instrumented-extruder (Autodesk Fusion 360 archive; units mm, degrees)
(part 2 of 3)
sketch "Sketch1" plane through (0, 0, 0) normal (0, 1, 0) x axis (1, 0, 0)
  line L1 (0, 10) -> (0, -2.75)
  line L2 (1.95, 10) -> (0, 10)
  line L3 (2.45, 9.5) -> (1.95, 10)
  line L4 (2.45, 0) -> (2.45, 9.5)
  line L5 (4.75, 0) -> (2.45, 0)
  line L6 (4.75, -0.6) -> (4.75, 0)
  line L7 (2, -2.75) -> (0, -2.75)
  arc A1 centre (0, 2.6419) radius 5.7508 clockwise from (4.75, -0.6) to (2, -2.75)
  point P1 (0, 0)
  point P10 (0, 2.6419)
  point P3 (0, 10)
  point P2 (0, -2.75)
  point P9 (2, -2.75)
  point P7 (4.75, 0)
  point P8 (4.75, -0.6)
  point P5 (2.45, 9.5)
  vertical L1
  perpendicular L1 L2
  perpendicular L2 L4
  perpendicular L4 L5
  perpendicular L5 L6
  perpendicular L1 L7
  coincident P1 L5
  coincident L1 P10
  coincident P1 L1
  dimension "d1" distance P1 P3 = 10
  dimension "d2" distance P1 P2 = 2.75
  dimension "d3" distance P2 P9 = 2 (= "( 4 / 2 ) * 1 mm")
  dimension "d4" distance P7 P8 = 0.6
  dimension "d5" distance L1 P7 = 4.75 (= "( 9.5 / 2 ) * 1 mm")
  dimension "d6" distance P1 L4 = 2.45 (= "( 4.9 / 2 ) * 1 mm")
  dimension "d7" angle L2 L3 = 45
  dimension "d8" distance L2 P5 = 0.5
revolve "Revolve1" sketch "Sketch1" AlongAngle 360
sketch "Sketch2" plane through (0, 0, 2.75) normal (0, 0, 1) x axis (-1, 0, 0)
  line L1 (0, -1.7321) -> (-1.5, -0.866)
  line L2 (1.5, -0.866) -> (0, -1.7321)
  line L3 (1.5, 0.866) -> (1.5, -0.866)
  line L4 (0, 1.7321) -> (1.5, 0.866)
  line L5 (-1.5, 0.866) -> (0, 1.7321)
  line L6 (-1.5, -0.866) -> (-1.5, 0.866)
  circle C1 centre (0, 0) radius 2
  point P2 (0, 0)
  point P9 (0, 0)
  point P5 (1.5, -0.866)
  coincident P2 P9
  vertical L3
  dimension "d10" distance P5 L6 = 3
extrude "Extrude1" cut sketch "Sketch2" profile of L1 L2 L3 L4 L5 L6 to an object offset 0.5

design "PP_SHFT_5x28-91585A562"
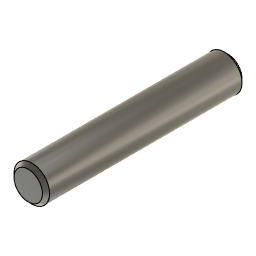
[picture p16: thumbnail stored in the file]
sketch "Sketch1" plane through (0, 0, 0) normal (0, 1, 0) x axis (1, 0, 0)
  circle C1 centre (0, 0) radius 2.5
  point P1 (0, 0)
  point P2 (0, 0)
  coincident P1 P2
  dimension "d1" diameter C1 = 5
extrude "Extrude1" new body sketch "Sketch1" along normal blind 28
chamfer "Chamfer1" distance 0.5

design "Pogo USB Stick"
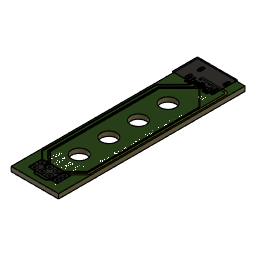
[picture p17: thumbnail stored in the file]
sketch "Outline" plane through (0, 0, 0) normal (0, 0, 1) x axis (1, 0, 0)
  line L1 (16, 0) -> (0, 0)
  line L2 (16, 63) -> (16, 0)
  line L3 (0, 63) -> (16, 63)
  line L4 (0, 0) -> (0, 63)
  line L5 (3.3811, 55.7439) -> (3.38, 55.77)
  line L6 (3.3846, 55.7179) -> (3.3811, 55.7439)
  line L7 (3.3902, 55.6924) -> (3.3846, 55.7179)
  line L8 (3.3981, 55.6674) -> (3.3902, 55.6924)
  line L9 (3.4081, 55.6432) -> (3.3981, 55.6674)
  line L10 (3.4202, 55.62) -> (3.4081, 55.6432)
  line L11 (3.4343, 55.5979) -> (3.4202, 55.62)
  line L12 (3.4502, 55.5772) -> (3.4343, 55.5979)
  line L13 (3.4679, 55.5579) -> (3.4502, 55.5772)
  line L14 (3.4872, 55.5402) -> (3.4679, 55.5579)
  line L15 (3.5079, 55.5243) -> (3.4872, 55.5402)
  line L16 (3.53, 55.5102) -> (3.5079, 55.5243)
  line L17 (3.5532, 55.4981) -> (3.53, 55.5102)
  line L18 (3.5774, 55.4881) -> (3.5532, 55.4981)
  line L19 (3.6024, 55.4802) -> (3.5774, 55.4881)
  line L20 (3.6279, 55.4746) -> (3.6024, 55.4802)
  line L21 (3.6539, 55.4711) -> (3.6279, 55.4746)
  line L22 (3.68, 55.47) -> (3.6539, 55.4711)
  line L23 (3.7061, 55.4711) -> (3.68, 55.47)
  line L24 (3.7321, 55.4746) -> (3.7061, 55.4711)
  line L25 (3.7576, 55.4802) -> (3.7321, 55.4746)
  line L26 (3.7826, 55.4881) -> (3.7576, 55.4802)
  line L27 (3.8068, 55.4981) -> (3.7826, 55.4881)
  line L28 (3.83, 55.5102) -> (3.8068, 55.4981)
  line L29 (3.8521, 55.5243) -> (3.83, 55.5102)
  line L30 (3.8728, 55.5402) -> (3.8521, 55.5243)
  line L31 (3.8921, 55.5579) -> (3.8728, 55.5402)
  line L32 (3.9098, 55.5772) -> (3.8921, 55.5579)
  line L33 (3.9257, 55.5979) -> (3.9098, 55.5772)
  line L34 (3.9398, 55.62) -> (3.9257, 55.5979)
  line L35 (3.9519, 55.6432) -> (3.9398, 55.62)
  line L36 (3.9619, 55.6674) -> (3.9519, 55.6432)
  line L37 (3.9698, 55.6924) -> (3.9619, 55.6674)
  line L38 (3.9754, 55.7179) -> (3.9698, 55.6924)
  line L39 (3.9789, 55.7439) -> (3.9754, 55.7179)
  line L40 (3.98, 55.77) -> (3.9789, 55.7439)
  line L41 (3.98, 56.87) -> (3.98, 55.77)
  line L42 (3.9789, 56.8961) -> (3.98, 56.87)
  line L43 (3.9754, 56.9221) -> (3.9789, 56.8961)
  line L44 (3.9698, 56.9476) -> (3.9754, 56.9221)
  line L45 (3.9619, 56.9726) -> (3.9698, 56.9476)
  line L46 (3.9519, 56.9968) -> (3.9619, 56.9726)
  line L47 (3.9398, 57.02) -> (3.9519, 56.9968)
  line L48 (3.9257, 57.0421) -> (3.9398, 57.02)
  line L49 (3.9098, 57.0628) -> (3.9257, 57.0421)
  line L50 (3.8921, 57.0821) -> (3.9098, 57.0628)
  line L51 (3.8728, 57.0998) -> (3.8921, 57.0821)
  line L52 (3.8521, 57.1157) -> (3.8728, 57.0998)
  line L53 (3.83, 57.1298) -> (3.8521, 57.1157)
  line L54 (3.8068, 57.1419) -> (3.83, 57.1298)
  line L55 (3.7826, 57.1519) -> (3.8068, 57.1419)
  line L56 (3.7576, 57.1598) -> (3.7826, 57.1519)
  line L57 (3.7321, 57.1654) -> (3.7576, 57.1598)
  line L58 (3.7061, 57.1689) -> (3.7321, 57.1654)
  line L59 (3.68, 57.17) -> (3.7061, 57.1689)
  line L60 (3.6539, 57.1689) -> (3.68, 57.17)
  line L61 (3.6279, 57.1654) -> (3.6539, 57.1689)
  line L62 (3.6024, 57.1598) -> (3.6279, 57.1654)
  line L63 (3.5774, 57.1519) -> (3.6024, 57.1598)
  line L64 (3.5532, 57.1419) -> (3.5774, 57.1519)
  line L65 (3.53, 57.1298) -> (3.5532, 57.1419)
  line L66 (3.5079, 57.1157) -> (3.53, 57.1298)
  line L67 (3.4872, 57.0998) -> (3.5079, 57.1157)
  line L68 (3.4679, 57.0821) -> (3.4872, 57.0998)
  line L69 (3.4502, 57.0628) -> (3.4679, 57.0821)
  line L70 (3.4343, 57.0421) -> (3.4502, 57.0628)
  line L71 (3.4202, 57.02) -> (3.4343, 57.0421)
  line L72 (3.4081, 56.9968) -> (3.4202, 57.02)
  line L73 (3.3981, 56.9726) -> (3.4081, 56.9968)
  line L74 (3.3902, 56.9476) -> (3.3981, 56.9726)
  line L75 (3.3846, 56.9221) -> (3.3902, 56.9476)
  line L76 (3.3811, 56.8961) -> (3.3846, 56.9221)
  line L77 (3.38, 56.87) -> (3.3811, 56.8961)
  line L78 (3.38, 55.77) -> (3.38, 56.87)
  line L79 (12.0211, 55.7439) -> (12.02, 55.77)
  line L80 (12.0246, 55.7179) -> (12.0211, 55.7439)
  line L81 (12.0302, 55.6924) -> (12.0246, 55.7179)
  line L82 (12.0381, 55.6674) -> (12.0302, 55.6924)
  line L83 (12.0481, 55.6432) -> (12.0381, 55.6674)
  line L84 (12.0602, 55.62) -> (12.0481, 55.6432)
  line L85 (12.0743, 55.5979) -> (12.0602, 55.62)
  line L86 (12.0902, 55.5772) -> (12.0743, 55.5979)
  line L87 (12.1079, 55.5579) -> (12.0902, 55.5772)
  line L88 (12.1272, 55.5402) -> (12.1079, 55.5579)
  line L89 (12.1479, 55.5243) -> (12.1272, 55.5402)
  line L90 (12.17, 55.5102) -> (12.1479, 55.5243)
  line L91 (12.1932, 55.4981) -> (12.17, 55.5102)
  line L92 (12.2174, 55.4881) -> (12.1932, 55.4981)
  line L93 (12.2424, 55.4802) -> (12.2174, 55.4881)
  line L94 (12.2679, 55.4746) -> (12.2424, 55.4802)
  line L95 (12.2939, 55.4711) -> (12.2679, 55.4746)
  line L96 (12.32, 55.47) -> (12.2939, 55.4711)
  line L97 (12.3461, 55.4711) -> (12.32, 55.47)
  line L98 (12.3721, 55.4746) -> (12.3461, 55.4711)
  line L99 (12.3976, 55.4802) -> (12.3721, 55.4746)
  line L100 (12.4226, 55.4881) -> (12.3976, 55.4802)
  line L101 (12.4468, 55.4981) -> (12.4226, 55.4881)
  line L102 (12.47, 55.5102) -> (12.4468, 55.4981)
  line L103 (12.4921, 55.5243) -> (12.47, 55.5102)
  line L104 (12.5128, 55.5402) -> (12.4921, 55.5243)
  line L105 (12.5321, 55.5579) -> (12.5128, 55.5402)
  line L106 (12.5498, 55.5772) -> (12.5321, 55.5579)
  line L107 (12.5657, 55.5979) -> (12.5498, 55.5772)
  line L108 (12.5798, 55.62) -> (12.5657, 55.5979)
  line L109 (12.5919, 55.6432) -> (12.5798, 55.62)
  line L110 (12.6019, 55.6674) -> (12.5919, 55.6432)
  line L111 (12.6098, 55.6924) -> (12.6019, 55.6674)
  line L112 (12.6154, 55.7179) -> (12.6098, 55.6924)
  line L113 (12.6189, 55.7439) -> (12.6154, 55.7179)
  line L114 (12.62, 55.77) -> (12.6189, 55.7439)
  line L115 (12.62, 56.87) -> (12.62, 55.77)
  line L116 (12.6189, 56.8961) -> (12.62, 56.87)
  line L117 (12.6154, 56.9221) -> (12.6189, 56.8961)
  line L118 (12.6098, 56.9476) -> (12.6154, 56.9221)
  line L119 (12.6019, 56.9726) -> (12.6098, 56.9476)
  line L120 (12.5919, 56.9968) -> (12.6019, 56.9726)
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canvas "Canvas1" bodies "Board"
canvas "Canvas2" bodies "Board"
pcbhole "PCBHole1" HoleDepth 1.605 HoleDiameter 5.25 TipAngle 10313.2
pcbhole "PCBHole2" HoleDepth 1.605 HoleDiameter 5.25 TipAngle 10313.2
pcbhole "PCBHole3" HoleDepth 1.605 HoleDiameter 5.25 TipAngle 10313.2
pcbhole "PCBHole4" HoleDepth 1.605 HoleDiameter 5.25 TipAngle 10313.2
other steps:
extrude "Extrude1" sketch "Outline" blind 1.5 bodies "Board"
pcbextrude "PCBExtrude1"
pcbextrude "PCBExtrude1"
pcbextrude "PCBExtrude1"
box_primitive "BoxPrimitive1" DistanceX 9.7028 DistanceY 4.6228 DistanceZ 0.1 OffsetDistanceX 0 OffsetDistanceY 0
box_primitive "BoxPrimitive1" DistanceX 13.575 DistanceY 8.48 DistanceZ 0.1 OffsetDistanceX 0 OffsetDistanceY 0
pcbextrude "PCBExtrude1"
pcbextrude "PCBExtrude1"
pcbhole "PCBHole1"
pcbhole "PCBHole1"
pcbhole "PCBHole1" HoleDepth 1.606 HoleDiameter 5.25 TipAngle 10313.2
pcbhole "PCBHole1" HoleDepth 1.606 HoleDiameter 5.25 TipAngle 10313.2
pcbextrude "PCBExtrude2" bodies "CopperHoles"
pcbhole "PCBHole2" HoleDepth 1.606 HoleDiameter 5.25 TipAngle 10313.2
pcbhole "PCBHole2" HoleDepth 1.606 HoleDiameter 5.25 TipAngle 10313.2
pcbhole "PCBHole3" HoleDepth 1.606 HoleDiameter 5.25 TipAngle 10313.2
pcbhole "PCBHole3" HoleDepth 1.606 HoleDiameter 5.25 TipAngle 10313.2
pcbhole "PCBHole1"
pcbhole "PCBHole4" HoleDepth 1.606 HoleDiameter 5.25 TipAngle 10313.2
pcbhole "PCBHole4" HoleDepth 1.606 HoleDiameter 5.25 TipAngle 10313.2
create_component "CreateComponent1"
create_component "CreateComponent2"
create_component "CreateComponent3"
create_component "CreateComponent4"
create_component "CreateComponent5"
create_component "CreateComponent6"
create_component "CreateComponent1"
create_component "CreateComponent2"
as_built_joint "As-built1"
named bodies: "Board", "CopperHoles"

design "HW_M5-Washer"
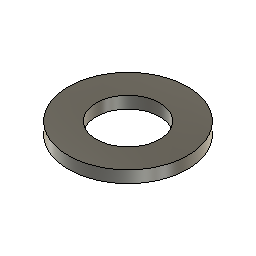
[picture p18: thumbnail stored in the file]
sketch "Sketch1" plane through (0, 0, 0) normal (0, 1, 0) x axis (1, 0, 0)
  line L1 (5, 0) -> (2.65, 0)
  line L2 (5, -1) -> (5, 0)
  line L3 (2.65, -1) -> (5, -1)
  line L4 (2.65, 0) -> (2.65, -1)
  point P1 (0, 0)
  point P2 (2.65, 0)
  point P5 (2.65, -1)
  horizontal L1
  vertical L2
  horizontal L3
  vertical L4
  coincident P1 L1
  dimension "d1" distance P2 P5 = 1
  dimension "d2" distance P1 L4 = 2.65 (= "( 5.3 / 2 ) * 1 mm")
  dimension "d3" distance P1 L2 = 5 (= "( 10 / 2 ) * 1 mm")
revolve "Revolve1" sketch "Sketch1" AlongAngle 360

design "AS_Tool-Blank" references "Pogo USB Stick", "HW_M5x10-BHCS", "HW_M5x08-BHCS", "HW_M5x10-SHCS"
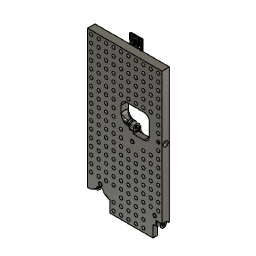
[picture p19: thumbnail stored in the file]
sketch "Profile" plane through (0, 0, 0) normal (1, 0, 0) x axis (0, 1, 0)
  line L1 (-10, 0) -> (0, 0)
  line L2 (-10, 200) -> (-10, 0)
  line L3 (0, 200) -> (-10, 200)
  line L4 (0, 0) -> (0, 200)
  line L5 (-5, 200) -> (-5, 0)
  line L6 (-0.8, 19.3115) -> (0, 19.3115)
  line L7 (-10, 22.4) -> (-5, 22.4)
  line L8 (-10, 15.7813) -> (-9.2, 15.7813)
  line L9 (0, 16.2825) -> (-1.6412, 14.6412)
  circle C1 centre (-5, 18) radius 2.2
  circle C2 centre (-5, 18) radius 4.25
  arc A1 centre (-5, 18) radius 4.4 clockwise from (-5, 22.4) to (-0.8, 19.3115)
  arc A2 centre (-5, 18) radius 4.75 clockwise from (-1.6412, 14.6412) to (-9.2, 15.7813)
  point P1 (0, 0)
  point P2 (0, 0)
  point P8 (-5, 0)
  point P9 (-5, 200)
  point P6 (-5, 18)
  point P10 (0, 19.3115)
  point P12 (-5, 18)
  point P14 (-10, 22.4)
  point P15 (-5, 18)
  point P18 (-10, 15.7813)
  point P19 (0, 16.2825)
  point P4 (-10, 200)
  point P5 (0, 200)
  point P3 (-10, 0)
  point P11 (-0.8, 19.3115)
  horizontal L1
  vertical L2
  horizontal L3
  vertical L4
  coincident P1 P2
  concentric C1 C2
  midpoint L1 P8
  midpoint L3 P9
  coincident P6 L5
  coincident L4 P10
  perpendicular L4 L6
  coincident P6 P12
  coincident L2 P14
  tangent A1 L7
  perpendicular L2 L7
  coincident P12 P15
  coincident L2 P18
  perpendicular L2 L8
  equal L6 L8
  coincident L4 P19
  tangent A2 L9
  dimension "d1" distance P4 P5 = 10
  dimension "d2" distance P3 P4 = 200
  dimension "d3" distance P3 P6 = 18
  dimension "d5" diameter C1 = 4.4
  dimension "d6" diameter C2 = 8.5
  dimension "d7" distance C2 A1 = 0.15
  dimension "d20" distance P10 P11 = 0.8
  dimension "d21" angle L5 L9 = 45
  dimension "d22" distance C2 A2 = 0.5
  dimension "d276" alignAngle = 0
  dimension "d277" alignOffsetX = 0
  dimension "d278" alignOffsetY = 0
  dimension "d279" alignOffsetZ = 1.6
  dimension "d280" alignAngle = 0
  dimension "d281" alignOffsetX = 0
  dimension "d282" alignOffsetY = 0
  dimension "d283" alignOffsetZ = 1.6
  dimension "d284" alignAngle = 0
  dimension "d285" alignOffsetX = 0
  dimension "d286" alignOffsetY = 0
  dimension "d287" alignOffsetZ = 1.6
extrude "Extrude1" new body sketch "Profile" profile of L1 L2 L3 L4 C1 L6 A1 L7 distance 100
sketch "Face" plane through (0, -10, 0) normal (0, -1, 0) x axis (1, 0, 0)
  line L1 (50, 0) -> (-50, 0)
  line L2 (50, 200) -> (50, 0)
  line L3 (-50, 200) -> (50, 200)
  line L4 (-50, 0) -> (-50, 200)
  line L5 (-45.5466, 15) -> (-50, 15)
  line L6 (-36.4534, 20.25) -> (-45.5466, 15)
  line L7 (-20.4534, 15) -> (-29.5466, 20.25)
  line L8 (-20, 0) -> (-20, 15)
  line L9 (-33, 3.7686) -> (-41, 17.625)
  line L10 (-33, 3.7686) -> (-25, 17.625)
  line L11 (-33, 14.2686) -> (-33, 3.7686)
  line L12 (-46.5, 27.1513) -> (-41, 17.625)
  line L13 (-20.4534, 15) -> (-20, 15)
  line L14 (0, 0) -> (0, 98)
  line L15 (6, 107.75) -> (6, 118.25)
  line L16 (33, 140) -> (33, 107.75)
  line L17 (-5, 140) -> (33, 140)
  line L18 (-5, 107.75) -> (-5, 140)
  line L19 (33, 107.75) -> (-5, 107.75)
  line L20 (10, 98) -> (10, 107.75)
  line L21 (10, 98) -> (0, 98)
  line L22 (-5, 118.25) -> (6, 118.25)
  arc A1 centre (-33, 14.2686) radius 6.9067 clockwise from (-36.4534, 20.25) to (-29.5466, 20.25)
  circle C1 centre (-33, 27) radius 2.2
  circle C2 centre (40, 27) radius 2.2
  circle C3 centre (-33, 27) radius 5
  circle C4 centre (40, 27) radius 5
  circle C5 centre (10, 98) radius 2.2
  circle C6 centre (10, 98) radius 5
  point P6 (-50, 15)
  point P12 (-20, 0)
  point P14 (-41, 17.625)
  point P16 (-25, 17.625)
  point P13 (-33, 14.2686)
  point P17 (-33, 14.2686)
  point P10 (-20.4534, 15)
  point P19 (-20.4534, 15)
  point P22 (0, 0)
  point P27 (0, 0)
  point P30 (6, 107.75)
  point P28 (10, 98)
  point P36 (10, 98)
  point P35 (10, 107.75)
  point P37 (10, 98)
  point P38 (-5, 118.25)
  point P39 (6, 113)
  point P9 (-29.5466, 20.25)
  point P18 (-46.5, 27.1513)
  point P2 (-50, 0)
  point P15 (-33, 3.7686)
  point P1 (0, 0)
  point P20 (-33, 27)
  point P21 (40, 27)
  point P29 (6, 118.25)
  point P31 (33, 107.75)
  point P32 (33, 140)
  point P25 (10, 98)
  point P26 (0, 98)
  point P34 (-5, 107.75)
  coincident L4 P6
  perpendicular L4 L5
  coincident L1 P12
  perpendicular L1 L8
  tangent L7 A1
  tangent L6 A1
  midpoint L6 P14
  perpendicular L6 L9
  midpoint L7 P16
  perpendicular L7 L10
  coincident P13 P17
  vertical L11
  coincident L5 P10
  perpendicular L6 L12
  perpendicular L8 L13
  coincident P10 P19
  concentric C1 C3
  concentric C2 C4
  equal C3 C4
  equal C1 C2
  coincident P22 P27
  vertical L14
  equal C2 C5
  concentric C5 C6
  equal C4 C6
  vertical L15
  perpendicular L16 L17
  perpendicular L16 L19
  coincident P30 L19
  horizontal L19
  coincident P28 P36
  vertical L20
  vertical L18
  coincident L19 P35
  coincident P28 P37
  perpendicular L20 L21
  coincident L18 P38
  perpendicular L18 L22
  midpoint L15 P39
  dimension "d35" radius A1 = 6.9067
  dimension "d37" distance P9 P10 = 10.5
  dimension "d39" distance P14 P18 = 11
  dimension "d40" distance P2 P6 = 15
  dimension "d41" angle L9 L11 = 30
  dimension "d42" distance P2 P15 = 17
  dimension "d43" distance P12 P15 = 13
  dimension "d45" distance P14 P16 = 16
  dimension "d46" distance P1 P20 = 33
  dimension "d47" distance P1 P21 = 40
  dimension "d48" distance P20 P22 = 27
  dimension "d51" distance P1 P21 = 27
  dimension "d52" diameter C2 = 4.4
  dimension "d53" diameter C4 = 10
  dimension "d101" distance P29 P30 = 10.5
  dimension "d188" distance P31 P32 = 32.25
  dimension "d189" distance P1 P31 = 107.75
  dimension "d193" distance P31 P35 = 23
  dimension "d214" distance P1 L17 = 140
  dimension "d215" distance P25 P27 = 98
  dimension "d216" distance P26 P37 = 10
  dimension "d217" distance P27 P39 = 113 (= "98 mm + 15 mm")
  dimension "d218" distance P35 P39 = 4
  dimension "d219" distance P26 P34 = 5
extrude "Extrude7" cut sketch "Face" profile of L1 L4 L5 L6 L7 L8 A1 L13 C1 C2 C5 L15 L16 L17 L18 L19 L22 to an object
hole "Hole1" HoleDepth 11 HoleDiameter 4.4 TipAngle 118 CSDiameter 5 CSAngle 90
hole "Hole2" HoleDepth 11 HoleDiameter 4.4 TipAngle 118 CSDiameter 5 CSAngle 90
extrude "Extrude4" sketch "Profile" profile of L1 L2 L4 C1 L6 A1 L7 A2 L8 L9 blind -8
extrude "Extrude5" sketch "Profile" profile of L1 L2 L4 A2 L8 L9 blind -4
extrude "Extrude6" sketch "Profile" profile of C1 blind -16.5
chamfer "Chamfer2" distance 0.5
fillet "Fillet1" radius 3.2
chamfer "Chamfer9" distance 0.5
chamfer "Chamfer3" distance 0.6
work_plane "WorkPlane1" sketch "Profile" AlongDistance -33
sketch "Left Cleat Slice" plane through (-33, 0, 0) normal (1, 0, 0) x axis (0, 1, 0)
  line L1 (-20.6308, 24.2665) -> (5.35, 9.2665)
  line L2 (-7.7792, 0) -> (0, 0)
  line L3 (-18.0058, 28.8131) -> (-20.6308, 24.2665)
  line L4 (7.975, 13.8131) -> (-18.0058, 28.8131)
  line L5 (5.35, 9.2665) -> (7.975, 13.8131)
  point P1 (0, 0)
  point P4 (0, 0)
  point P2 (5.35, 9.2665)
  point P8 (5.35, 9.2665)
  point P3 (-20.6308, 24.2665)
  point P6 (-18.0058, 28.8131)
  coincident P1 P4
  horizontal L2
  perpendicular L1 L3
  perpendicular L3 L4
  perpendicular L1 L5
  coincident P2 P8
  coincident P1 L5
  dimension "d159" angle L1 L2 = 30
  dimension "d160" distance P3 P6 = 5.25
  dimension "d161" distance P1 L1 = 10.7
  dimension "d162" distance P2 P3 = 30
revolve "Revolve1" sketch "Left Cleat Slice" AlongAngle 360
sketch "Sketch12" plane through (6, 0, 0) normal (1, 0, 0) x axis (0, 1, 0)
  line L1 (0, 118.25) -> (0, 107.75)
  line L2 (-10, 118.25) -> (0, 118.25)
  line L3 (-10, 107.75) -> (-10, 118.25)
  line L4 (0, 107.75) -> (-10, 107.75)
  line L5 (0, 113) -> (-10, 113)
  line L6 (0, 114.7175) -> (-1.6412, 116.3588)
  line L7 (-10, 113.8397) -> (-9.1136, 115.375)
  line L8 (0, 112.8603) -> (-1.1895, 110.8)
  line L9 (-10, 110.8061) -> (-7.2, 109.1895)
  circle C1 centre (-5, 113) radius 2.2
  arc A1 centre (-5, 113) radius 4.75 clockwise from (-9.1136, 115.375) to (-1.6412, 116.3588)
  circle C2 centre (-5, 113) radius 4.25
  arc A2 centre (-5, 113) radius 4.4 clockwise from (-1.1895, 110.8) to (-7.2, 109.1895)
  point P6 (-10, 113)
  point P7 (0, 113)
  point P8 (-5, 113)
  point P9 (-5, 113)
  point P12 (0, 114.7175)
  point P14 (-10, 113.8397)
  point P15 (-5, 113)
  point P18 (0, 112.8603)
  point P19 (-10, 110.8061)
  midpoint L3 P6
  midpoint L1 P7
  midpoint L5 P8
  coincident P8 P9
  tangent A1 L6
  coincident L1 P12
  concentric C1 C2
  coincident L3 P14
  tangent A1 L7
  coincident P8 P15
  coincident L1 P18
  tangent A2 L8
  coincident L3 P19
  tangent A2 L9
  dimension "d220" diameter C1 = 4.4
  dimension "d223" angle L1 L6 = 45
  dimension "d225" diameter C2 = 8.5
  dimension "d226" distance A1 C2 = 0.5
  dimension "d227" angle L3 L7 = 30
  dimension "d235" angle L1 L8 = 30
  dimension "d236" distance C2 A2 = 0.15
  dimension "d237" angle L3 L9 = 60
extrude "Extrude21" cut sketch "Sketch12" profile of C1 against normal blind 16
extrude "Extrude22" cut sketch "Sketch12" profile of L1 L2 L3 A1 L6 L7 to an object
chamfer "Chamfer19" distance 0.5 distance 1.5
chamfer "Chamfer20" distance 0.5
extrude "Extrude23" add sketch "Sketch12" profile of L1 L3 L4 A2 L8 L9 along normal blind 5.5
chamfer "Chamfer21" distance 0.4
extrude "Extrude24" cut sketch "Sketch12" profile of C1 to an object
offset_faces "OffsetFaces2" distance -1.25
chamfer "Chamfer23" distance 4
component_insert "Component Insert1"
component_insert "Component Insert2"
component_insert "Component Insert3"
component_insert "Component Insert4"
component_insert "Component Insert5"
joint "Assemble1" alignAngle 180 alignOffsetX 0 alignOffsetY 0 alignOffsetZ 0
joint "Assemble2" alignAngle 180 alignOffsetX 0 alignOffsetY 0 alignOffsetZ 0
joint "Assemble3" alignAngle 0 alignOffsetX 0 alignOffsetY 0 alignOffsetZ 0
joint "Assemble4" alignAngle 0 alignOffsetX 0 alignOffsetY 0 alignOffsetZ 0
joint "Assemble5" alignAngle 0 alignOffsetX 0 alignOffsetY 0 alignOffsetZ 0
component_insert "Component Insert6"
component_insert "Component Insert7"
joint "Assemble6" alignAngle 180 alignOffsetX 0 alignOffsetY 0 alignOffsetZ 0
joint "Assemble8" alignAngle 180 alignOffsetX 0 alignOffsetY 0 alignOffsetZ 0
sketch "Sketch10" plane through (0, 0, 0) normal (0, 1, 0) x axis (1, 0, 0)
  dimension "d180" = 5
  dimension "d181" = 12.5
  dimension "d182" = 22.5
extrude "Extrude16" sketch "Sketch10" blind -0.6
chamfer "Chamfer22" distance 3
fillet "Fillet9" ChordLen 10
fillet "Fillet10" ChordLen 5
fillet "Fillet11" ChordLen 5
sketch "Grid" plane through (0, 0, 0) normal (0, 1, 0) x axis (1, 0, 0)
  circle C1 centre (-45, -5) radius 2.2
  circle C2 centre (-35, -5) radius 2.2
  circle C3 centre (-25, -5) radius 2.2
  circle C4 centre (-15, -5) radius 2.2
  circle C5 centre (-5, -5) radius 2.2
  circle C6 centre (5, -5) radius 2.2
  circle C7 centre (15, -5) radius 2.2
  circle C8 centre (25, -5) radius 2.2
  circle C9 centre (35, -5) radius 2.2
  circle C10 centre (45, -5) radius 2.2
  circle C11 centre (-45, -15) radius 2.2
  circle C12 centre (-35, -15) radius 2.2
  circle C13 centre (-25, -15) radius 2.2
  circle C14 centre (-15, -15) radius 2.2
  circle C15 centre (-5, -15) radius 2.2
  circle C16 centre (5, -15) radius 2.2
  circle C17 centre (15, -15) radius 2.2
  circle C18 centre (25, -15) radius 2.2
  circle C19 centre (35, -15) radius 2.2
  circle C20 centre (45, -15) radius 2.2
  circle C21 centre (-45, -25) radius 2.2
  circle C22 centre (-35, -25) radius 2.2
  circle C23 centre (-25, -25) radius 2.2
  circle C24 centre (-15, -25) radius 2.2
  circle C25 centre (-5, -25) radius 2.2
  circle C26 centre (5, -25) radius 2.2
  circle C27 centre (15, -25) radius 2.2
  circle C28 centre (25, -25) radius 2.2
  circle C29 centre (35, -25) radius 2.2
  circle C30 centre (45, -25) radius 2.2
  circle C31 centre (-45, -35) radius 2.2
  circle C32 centre (-35, -35) radius 2.2
  circle C33 centre (-25, -35) radius 2.2
  circle C34 centre (-15, -35) radius 2.2
  circle C35 centre (-5, -35) radius 2.2
  circle C36 centre (5, -35) radius 2.2
  circle C37 centre (15, -35) radius 2.2
  circle C38 centre (25, -35) radius 2.2
  circle C39 centre (35, -35) radius 2.2
  circle C40 centre (45, -35) radius 2.2
  circle C41 centre (-45, -45) radius 2.2
  circle C42 centre (-35, -45) radius 2.2
  circle C43 centre (-25, -45) radius 2.2
  circle C44 centre (-15, -45) radius 2.2
  circle C45 centre (-5, -45) radius 2.2
  circle C46 centre (5, -45) radius 2.2
  circle C47 centre (15, -45) radius 2.2
  circle C48 centre (25, -45) radius 2.2
  circle C49 centre (35, -45) radius 2.2
  circle C50 centre (45, -45) radius 2.2
  circle C51 centre (-45, -55) radius 2.2
  circle C52 centre (-35, -55) radius 2.2
  circle C53 centre (-25, -55) radius 2.2
  circle C54 centre (-15, -55) radius 2.2
  circle C55 centre (-5, -55) radius 2.2
  circle C56 centre (5, -55) radius 2.2
  circle C57 centre (15, -55) radius 2.2
  circle C58 centre (25, -55) radius 2.2
  circle C59 centre (35, -55) radius 2.2
  circle C60 centre (45, -55) radius 2.2
  circle C61 centre (-45, -65) radius 2.2
  circle C62 centre (-35, -65) radius 2.2
  circle C63 centre (-25, -65) radius 2.2
  circle C64 centre (-15, -65) radius 2.2
  circle C65 centre (-5, -65) radius 2.2
  circle C66 centre (5, -65) radius 2.2
  circle C67 centre (15, -65) radius 2.2
  circle C68 centre (25, -65) radius 2.2
  circle C69 centre (35, -65) radius 2.2
  circle C70 centre (45, -65) radius 2.2
  circle C71 centre (-45, -75) radius 2.2
  circle C72 centre (-35, -75) radius 2.2
  circle C73 centre (-25, -75) radius 2.2
  circle C74 centre (-15, -75) radius 2.2
  circle C75 centre (-5, -75) radius 2.2
  circle C76 centre (5, -75) radius 2.2
  circle C77 centre (15, -75) radius 2.2
  circle C78 centre (25, -75) radius 2.2
  circle C79 centre (35, -75) radius 2.2
  circle C80 centre (45, -75) radius 2.2
  circle C81 centre (-45, -85) radius 2.2
  circle C82 centre (-35, -85) radius 2.2
  circle C83 centre (-25, -85) radius 2.2
  circle C84 centre (-15, -85) radius 2.2
  circle C85 centre (-5, -85) radius 2.2
  circle C86 centre (5, -85) radius 2.2
  circle C87 centre (15, -85) radius 2.2
  circle C88 centre (25, -85) radius 2.2
  circle C89 centre (35, -85) radius 2.2
  circle C90 centre (45, -85) radius 2.2
  circle C91 centre (-45, -95) radius 2.2
  circle C92 centre (-35, -95) radius 2.2
  circle C93 centre (-25, -95) radius 2.2
  circle C94 centre (-15, -95) radius 2.2
  circle C95 centre (-5, -95) radius 2.2
  circle C96 centre (5, -95) radius 2.2
  circle C97 centre (15, -95) radius 2.2
  circle C98 centre (25, -95) radius 2.2
  circle C99 centre (35, -95) radius 2.2
  circle C100 centre (45, -95) radius 2.2
  circle C101 centre (-45, -105) radius 2.2
  circle C102 centre (-35, -105) radius 2.2
  circle C103 centre (-25, -105) radius 2.2
  circle C104 centre (-15, -105) radius 2.2
  circle C105 centre (-5, -105) radius 2.2
  circle C106 centre (5, -105) radius 2.2
  circle C107 centre (15, -105) radius 2.2
  circle C108 centre (25, -105) radius 2.2
  circle C109 centre (35, -105) radius 2.2
  circle C110 centre (45, -105) radius 2.2
  circle C111 centre (-45, -115) radius 2.2
  circle C112 centre (-35, -115) radius 2.2
  circle C113 centre (-25, -115) radius 2.2
  circle C114 centre (-15, -115) radius 2.2
  circle C115 centre (-5, -115) radius 2.2
  circle C116 centre (5, -115) radius 2.2
  circle C117 centre (15, -115) radius 2.2
  circle C118 centre (25, -115) radius 2.2
  circle C119 centre (35, -115) radius 2.2
  circle C120 centre (45, -115) radius 2.2
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  point P1 (0, 0)
  point P2 (-45, -5)
  dimension "d70" distance P1 P2 = 45
  dimension "d71" distance P1 P2 = 5
  dimension "d72" diameter C1 = 4.4
  dimension "d75" R-Pattern1-uDistance = 10
  dimension "d76" R-Pattern1-vDistance = -10
extrude "Extrude15" cut sketch "Grid" to an object
component_insert "Component Insert13"
joint "Assemble15" alignAngle 0 alignOffsetX 0 alignOffsetY 0 alignOffsetZ 0
component_insert "Component Insert14"
joint "Assemble16" alignAngle 0 alignOffsetX 0 alignOffsetY 0 alignOffsetZ 0
component_insert "Component Insert15"
joint "Assemble17" alignAngle 0 alignOffsetX 0 alignOffsetY 0 alignOffsetZ 0
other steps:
joint_origin "JointOrigin1"
joint_origin "JointOrigin2"
joint_origin "JointOrigin3"
joint_origin "JointOrigin4"
joint_origin "JointOrigin5"
joint_origin "JointOrigin6"
joint_origin "JointOrigin10"
joint_origin "JointOrigin22"
named bodies: "HP-Tool-Blank"

design "PP_SPRN_5-10-25_1804N11"
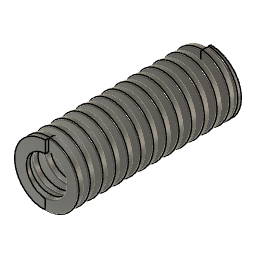
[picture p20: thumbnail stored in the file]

design "AS_Hotend-Extruder" references "PP_SPRN_5-10-25_1804N11", "HW_M5-Washer", "PP_TRNS_Bondtech-Mini-Gears", "HW_M5x60-SHCS", "PP_ACTU_N17-Stepper"
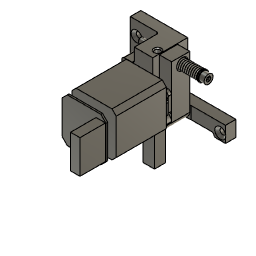
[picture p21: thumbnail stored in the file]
sketch "Sketch1" plane through (0, 0, 0) normal (0, 1, 0) x axis (1, 0, 0)
  line L1 (16.9, -21.15) -> (-25.4, -21.15)
  line L2 (16.9, 21.15) -> (16.9, -21.15)
  line L3 (-25.4, 21.15) -> (16.9, 21.15)
  line L4 (-25.4, -21.15) -> (-25.4, 21.15)
  line L5 (16.9, 21.15) -> (-25.4, -21.15)
  line L6 (-25.4, 21.15) -> (16.9, -21.15)
  line L7 (4.25, 0) -> (-4.25, 0)
  line L8 (11.25, -15.5) -> (-19.75, -15.5)
  line L9 (11.25, 15.5) -> (11.25, -15.5)
  line L10 (-19.75, 15.5) -> (11.25, 15.5)
  line L11 (-19.75, -15.5) -> (-19.75, 15.5)
  line L12 (4.25, 0) -> (4.25, 4.5)
  line L13 (6.25, 4.5) -> (4.25, 4.5)
  line L14 (6.25, 15.5) -> (6.25, 4.5)
  line L15 (16.25, -35) -> (16.25, 15.5)
  line L16 (4.6265, -35) -> (16.25, -35)
  line L17 (4.6265, -4.4842) -> (4.6265, -35)
  line L18 (7.8765, -8) -> (13, -4)
  line L19 (16.25, 9.25) -> (6.25, 9.25)
  line L20 (16.25, 9.5) -> (6.25, 9.5)
  line L21 (16.25, -11.25) -> (4.6265, -11.25)
  line L22 (16.25, -11.5) -> (4.6265, -11.5)
  line L23 (-13.75, -35) -> (3.8765, -35)
  line L24 (-13.75, -21.4) -> (-13.75, -35)
  line L25 (-41, -21.4) -> (-13.75, -21.4)
  line L26 (-41, 21.4) -> (-41, -21.4)
  line L27 (5.5, 21.4) -> (-41, 21.4)
  line L28 (5.5, 5.25) -> (5.5, 21.4)
  line L29 (4.25, 5.25) -> (5.5, 5.25)
  line L30 (3.8765, -35) -> (3.8765, -5.2367)
  line L31 (0.25, 3.4004) -> (-0.25, 3.4004)
  line L32 (0, 3.4004) -> (0, 0)
  line L33 (17.15, 21.4) -> (5.5, 21.4)
  line L34 (17.15, 9.6) -> (17.15, 21.4)
  line L35 (5.5, 9.6) -> (17.15, 9.6)
  line L36 (-25.65, 21.4) -> (-25.65, -21.4)
  line L37 (-35, -21.6) -> (-35, 8.4)
  line L38 (-0.25, -3.4004) -> (0.25, -3.4004)
  line L39 (-41, -35) -> (-41, -21.4)
  line L40 (-13.75, -35) -> (-41, -35)
  line L41 (51.25, 9.6) -> (17.15, 9.6)
  line L42 (51.25, 24.65) -> (51.25, 9.6)
  line L43 (38.75, 24.65) -> (51.25, 24.65)
  line L44 (38.75, 21.4) -> (38.75, 24.65)
  line L45 (17.15, 21.4) -> (38.75, 21.4)
  circle C1 centre (-4.25, 0) radius 4.75
  circle C2 centre (4.25, 0) radius 4.75
  circle C3 centre (4.25, 0) radius 1.5
  circle C4 centre (-4.25, 0) radius 11.125
  circle C5 centre (-19.75, -15.5) radius 1.75
  circle C6 centre (-19.75, 15.5) radius 1.75
  circle C7 centre (11.25, 15.5) radius 1.75
  circle C8 centre (11.25, -15.5) radius 1.75
  circle C9 centre (11.25, 15.5) radius 3.1
  arc A1 centre (4.25, 0) radius 4.5 clockwise from (4.6265, -4.4842) to (4.25, 4.5)
  arc A2 centre (11.25, 15.5) radius 5 clockwise from (6.25, 15.5) to (16.25, 15.5)
  circle C10 centre (7.8765, -8) radius 1.35
  circle C11 centre (7.8765, -8) radius 1.625
  circle C12 centre (7.8765, -8) radius 3
  circle C13 centre (13, -4) radius 1.35
  circle C14 centre (13, -4) radius 1.625
  circle C15 centre (13, -4) radius 3
  circle C16 centre (9.5, 6) radius 1.35
  circle C17 centre (9.5, 6) radius 1.625
  circle C18 centre (9.5, 6) radius 3
  arc A3 centre (-4.25, 0) radius 5.25 clockwise from (0, -3.0822) to (-0.25, 3.4004)
  arc A4 centre (4.25, 0) radius 5.25 clockwise from (0.25, 3.4004) to (4.25, 5.25)
  arc A5 centre (4.25, 0) radius 5.25 clockwise from (3.8765, -5.2367) to (0, -3.0822)
  circle C19 centre (-35, -21.6) radius 2.75
  circle C20 centre (-35, 8.4) radius 2.75
  circle C21 centre (-35, 8.4) radius 5.25
  circle C22 centre (-35, -21.6) radius 5.25
  arc A6 centre (4.25, 0) radius 5.25 clockwise from (6.25, 4.8541) to (4.6265, -5.2365)
  circle C23 centre (-19.75, -15.5) radius 3.25
  circle C24 centre (-19.75, 15.5) radius 3.25
  circle C25 centre (11.25, 15.5) radius 3.25
  circle C26 centre (45, 18.4) radius 2.75
  circle C27 centre (45, 18.4) radius 5.25
  circle C28 centre (45, 18.4) radius 6.25
  point P6 (-4.25, 0)
  point P7 (-4.25, 0)
  point P1 (0, 0)
  point P9 (-4.25, 0)
  point P8 (4.25, 0)
  point P10 (4.25, 0)
  point P15 (11.25, 15.5)
  point P13 (-19.75, -15.5)
  point P14 (11.25, -15.5)
  point P17 (-19.75, -15.5)
  point P16 (-19.75, 15.5)
  point P18 (-19.75, 15.5)
  point P19 (11.25, 15.5)
  point P20 (11.25, -15.5)
  point P22 (4.25, 0)
  point P25 (4.25, 0)
  point P30 (6.25, 15.5)
  point P28 (11.25, 15.5)
  point P27 (6.25, 15.5)
  point P29 (16.25, 15.5)
  point P37 (13, -4)
  point P40 (13, -4)
  point P34 (7.8765, -8)
  point P41 (7.8765, -8)
  point P24 (4.6265, -4.4842)
  point P33 (4.6265, -4.4842)
  point P45 (6.25, 9.25)
  point P46 (16.25, 9.25)
  point P47 (6.25, 9.5)
  point P48 (16.25, 9.5)
  point P49 (4.6265, -11.25)
  point P50 (16.25, -11.25)
  point P51 (4.6265, -11.5)
  point P52 (16.25, -11.5)
  point P53 (3.8765, -35)
  point P62 (3.8765, -35)
  point P63 (-4.25, 0)
  point P66 (4.25, 0)
  point P68 (4.25, 0)
  point P61 (3.8765, -5.2367)
  point P69 (3.8765, -5.2367)
  point P70 (0, 0)
  point P71 (0, 3.4004)
  point P60 (4.25, 5.25)
  point P32 (4.6265, -35)
  point P74 (5.5, 9.6)
  point P75 (-25.65, -21.4)
  point P76 (-25.65, 21.4)
  point P78 (-35, 8.4)
  point P79 (-35, 8.4)
  point P77 (-35, -21.6)
  point P80 (-35, -21.6)
  point P84 (4.6265, -5.2365)
  point P83 (4.25, 0)
  point P85 (6.25, 4.8541)
  point P89 (0.25, -3.4004)
  point P90 (-0.25, -3.4004)
  point P54 (-13.75, -35)
  point P92 (-13.75, -35)
  point P95 (51.25, 9.6)
  point P96 (51.25, 9.6)
  point P72 (17.15, 21.4)
  point P101 (17.15, 21.4)
  point P2 (-25.4, -21.15)
  point P5 (-25.4, 21.15)
  point P38 (13, -4)
  point P35 (7.8765, -8)
  point P11 (4.25, 0)
  point P43 (9.5, 6)
  point P44 (9.5, 6)
  point P12 (-4.25, 0)
  point P26 (6.25, 4.5)
  point P64 (-0.25, 3.4004)
  point P67 (0.25, 3.4004)
  point P31 (16.25, -35)
  point P21 (11.25, 15.5)
  point P56 (-41, -21.4)
  point P57 (-41, 21.4)
  point P81 (-35, 8.4)
  point P36 (7.8765, -8)
  point P39 (13, -4)
  point P93 (45, 18.4)
  horizontal L1
  perpendicular L1 L2
  parallel L1 L3
  parallel L2 L4
  coincident L5 P6
  coincident L6 P6
  equal L1 L4
  coincident P6 P7
  horizontal L7
  midpoint P1 L7
  coincident P6 P9
  coincident P8 P10
  equal C1 C2
  concentric C2 C3
  concentric C1 C4
  horizontal L8
  vertical L9
  horizontal L10
  vertical L11
  coincident L5 P15
  coincident L5 P13
  coincident L6 P14
  equal C5 C7
  equal C5 C6
  equal C6 C8
  coincident P13 P17
  coincident P16 P18
  coincident P15 P19
  coincident P14 P20
  concentric C7 C9
  coincident P10 P22
  coincident P10 P25
  vertical L12
  tangent A1 L13
  perpendicular L13 L14
  coincident L10 P30
  coincident P19 P28
  coincident P27 P30
  coincident L10 P29
  tangent A2 L15
  perpendicular L2 L16
  perpendicular L8 L17
  concentric C10 C11
  concentric C10 C12
  concentric C13 C14
  concentric C13 C15
  equal C10 C13
  equal C11 C14
  equal C12 C15
  coincident P37 P40
  coincident P34 P41
  coincident P24 P33
  concentric C16 C17
  concentric C16 C18
  equal C12 C18
  equal C10 C16
  equal C11 C17
  coincident L14 P45
  coincident L15 P46
  perpendicular L15 L19
  coincident L14 P47
  coincident L15 P48
  perpendicular L15 L20
  coincident L17 P49
  coincident L15 P50
  perpendicular L15 L21
  coincident L17 P51
  coincident L15 P52
  perpendicular L15 L22
  parallel L1 L23
  perpendicular L1 L24
  perpendicular L24 L25
  perpendicular L25 L26
  perpendicular L26 L27
  perpendicular L10 L28
  perpendicular L28 L29
  perpendicular L1 L30
  coincident P53 P62
  coincident P9 P63
  coincident P10 P66
  coincident P10 P68
  coincident P61 P69
  horizontal L31
  coincident P1 P70
  midpoint L31 P71
  vertical L32
  coincident L12 P60
  coincident P32 L23
  perpendicular L2 L33
  perpendicular L3 L34
  coincident L28 P74
  perpendicular L28 L35
  coincident L25 P75
  coincident L27 P76
  perpendicular L27 L36
  coincident P78 P79
  coincident P77 P80
  vertical L37
  concentric C20 C21
  equal C19 C20
  concentric C19 C22
  equal C21 C22
  coincident L17 P84
  coincident P66 P83
  coincident L14 P85
  concentric C5 C23
  concentric C6 C24
  equal C23 C24
  concentric C9 C25
  coincident A5 P89
  coincident A3 P90
  horizontal L38
  equal L31 L38
  perpendicular L25 L39
  perpendicular L26 L40
  coincident P54 P92
  concentric C26 C27
  equal C20 C26
  equal C21 C27
  perpendicular L34 L41
  concentric C26 C28
  tangent L42 C28
  coincident P95 P96
  vertical L42
  perpendicular L42 L43
  perpendicular L42 L45
  coincident P72 P101
  perpendicular L44 L45
  tangent C28 L44
  tangent C28 L43
  dimension "d1" distance P2 P5 = 42.3
  dimension "d2" distance P7 P8 = 8.5
  dimension "d3" diameter C1 = 9.5
  dimension "d4" diameter C3 = 3
  dimension "d5" diameter C4 = 22.25
  dimension "d6" distance P13 P16 = 31
  dimension "d7" diameter C5 = 3.5
  dimension "d8" diameter C9 = 6.2
  dimension "d9" radius A1 = 4.5
  dimension "d10" radius A2 = 5
  dimension "d11" diameter C10 = 2.7
  dimension "d12" diameter C11 = 3.25
  dimension "d13" diameter C12 = 6
  dimension "d18" distance L15 P38 = 3.25
  dimension "d19" distance L17 P35 = 3.25
  dimension "d21" distance P11 P43 = 6
  dimension "d22" distance L14 P44 = 3.25 (= "d19")
  dimension "d23" distance P43 L19 = 3.25 (= "d19")
  dimension "d24" distance P46 L20 = 0.25
  dimension "d25" distance P50 P52 = 0.25 (= "d24")
  dimension "d27" distance P12 L16 = 35
  dimension "d28" distance P26 L28 = 0.75
  dimension "d30" distance P64 P67 = 0.5
  dimension "d31" distance C2 A4 = 0.5
  dimension "d32" distance C2 A5 = 0.5 (= "d31")
  dimension "d33" distance L17 L30 = 0.75 (= "d28")
  dimension "d34" distance P31 P54 = 30
  dimension "d35" distance L3 L27 = 0.25
  dimension "d36" distance P21 L33 = 5.9
  dimension "d37" distance P21 L35 = 5.9 (= "d36")
  dimension "d38" distance P21 L34 = 5.9 (= "d36")
  dimension "d39" distance P56 P57 = 42.8 (= "42.3 mm + 0.5 mm")
  dimension "d40" distance P5 L36 = 0.25
  dimension "d41" distance P79 P80 = 30
  dimension "d43" distance P1 L37 = 35
  dimension "d44" distance L26 P81 = 6
  dimension "d45" diameter C20 = 5.5
  dimension "d46" distance C19 C22 = 2.5
  dimension "d50" distance C2 A6 = 0.5
  dimension "d68" distance C5 C23 = 1.5
  dimension "d69" diameter C23 = 6.5
  dimension "d86" distance C7 C25 = 1.5
  dimension "d146" distance P11 P35 = 8
  dimension "d147" distance P35 L21 = 3.25 (= "d19")
  dimension "d148" distance P36 P39 = 4
  dimension "d149" distance P40 P41 = 6.5
  dimension "d194" distance L27 P81 = 13
  dimension "d206" distance P1 P93 = 45
  dimension "d207" distance C27 C28 = 1
  dimension "d210" distance P81 P93 = 10
extrude "Extrude1" new body sketch "Sketch1" profile of C3 C4 A1 L13 L14 L15 L17 C11 C14 C17 L19 L21 blind 3 from offset 2.4
extrude "Extrude2" sketch "Sketch1" profile of C4 L14 L15 L17 C10 C11 C13 C14 C16 C17 L19 L21 A6 blind 14.4 from offset 0.2
extrude "Extrude3" sketch "Sketch1" profile of C3 C4 A1 L13 L14 L15 L17 C10 C11 C13 C14 C16 C17 L19 L21 A6 blind 3
extrude "Extrude4" sketch "Sketch1" profile of C9 L14 A2 L15 L16 L17 L19 L20 L21 L22 L35 C25 to an object
extrude "Extrude5" add sketch "Sketch1" profile of C9 L14 A2 L15 L20 L35 C25 to an object from offset 0.25
fillet "Fillet1" radius 5
fillet "Fillet2" radius 3.25
chamfer "Chamfer1" sketch "Sketch1" distance 1.5
fillet "Fillet4" sketch "Sketch1" radius 2
fillet "Fillet5" radius 2
chamfer "Chamfer4" distance 0.4
extrude "Extrude11" new body sketch "Sketch1" profile of C4 C5 C6 L23 L24 L25 L27 L28 L30 L36 C21 C22 C23 C24 along normal blind 33.4
extrude "Extrude12" add sketch "Sketch1" profile of C7 C9 L14 A2 L15 L28 L33 L34 L35 C25 to an object from offset 25
extrude "Extrude13" sketch "Sketch1" profile of C9 L14 A2 L15 L28 L33 L34 L35 C25 to an object from offset 0.25
extrude "Extrude14" cut sketch "Sketch1" profile of C5 C6 C7 C9 C23 C24 C25 blind 27 from offset 27
chamfer "Chamfer5" sketch "Sketch1" distance 1.5
chamfer "Chamfer6" sketch "Sketch1" distance 0.5
extrude "Extrude15" add sketch "Sketch1" profile of C4 L28 L29 L30 A3 A4 A5 L31 L38 to an object from offset 2.4
fillet "Fillet6" sketch "Sketch1" radius 1
chamfer "Chamfer7" sketch "Sketch1" distance 0.5
extrude "Extrude16" sketch "Sketch1" profile of L24 L25 L26 L27 L34 L36 C19 C20 C21 C22 L39 L40 C26 L41 L42 blind -10
sketch "Sketch2" plane through (0, 0, 35) normal (0, 0, 1) x axis (-1, 0, 0)
  line L1 (-3.8765, 0) -> (13.75, 0)
  line L2 (-3.8765, -33.4) -> (-3.8765, 0)
  line L3 (41, -33.4) -> (-3.8765, -33.4)
  line L4 (13.75, 0) -> (13.75, -23.4)
  line L5 (0, 0) -> (0, -8.4)
  line L6 (41, -23.4) -> (41, -33.4)
  line L7 (13.75, -23.4) -> (41, -23.4)
  circle C1 centre (0, -8.4) radius 1
  circle C2 centre (0, -8.4) radius 2.625
  point P7 (0, -8.4)
  point P8 (0, -8.4)
  point P1 (0, 0)
  point P9 (0, 0)
  point P6 (0, -8.4)
  concentric C1 C2
  coincident P7 P8
  coincident P1 P9
  vertical L5
  dimension "d120" diameter C2 = 5.25
  dimension "d121" diameter C1 = 2
  dimension "d122" distance L3 P6 = 25
extrude "Extrude17" cut sketch "Sketch2" profile of C1 to an object
extrude "Extrude18" cut sketch "Sketch2" profile of C1 C2 to an object
chamfer "Chamfer10" distance 1
extrude "Extrude19" sketch "Sketch2" profile of C1 C2 to an object
chamfer "Chamfer8" distance 1.15
chamfer "Chamfer9" distance 0.5
sketch "Sketch3" plane through (16.25, 0, 0) normal (1, 0, 0) x axis (0, 1, 0)
  line L1 (0.25, -14.5) -> (5.6, -14.5)
  line L2 (0.25, -15.5) -> (0.25, -14.5)
  line L3 (23, -15.5) -> (0.25, -15.5)
  line L4 (23, 35) -> (23, -15.5)
  line L5 (5.6, 35) -> (23, 35)
  line L6 (5.6, -14.5) -> (5.6, 35)
  line L7 (11.3812, 28) -> (13.6906, 32)
  line L8 (13.6906, 24) -> (11.3812, 28)
  line L9 (18.3094, 24) -> (13.6906, 24)
  line L10 (20.6188, 28) -> (18.3094, 24)
  line L11 (18.3094, 32) -> (20.6188, 28)
  line L12 (13.6906, 32) -> (18.3094, 32)
  circle C1 centre (16, 28) radius 2.875
  circle C2 centre (16, 28) radius 5.5
  circle C3 centre (16, 28) radius 2.625
  point P8 (16, 28)
  point P15 (16, 28)
  point P18 (16, 28)
  point P11 (13.6906, 24)
  point P16 (8.4, 35)
  coincident P8 P15
  horizontal L12
  concentric C1 C2
  coincident P15 P18
  dimension "d132" diameter C1 = 5.75
  dimension "d133" distance P11 L12 = 8
  dimension "d134" distance L5 P15 = 7
  dimension "d135" distance P15 P16 = 7.6
  dimension "d136" distance L4 P15 = 7
  dimension "d137" diameter C2 = 11
  dimension "d161" diameter C3 = 5.25
extrude "Extrude20" cut sketch "Sketch3" profile of C3 to an object
extrude "Extrude24" cut sketch "Sketch3" + "Sketch1" profile of S1:C1 S1:C3 to an object
extrude "Extrude21" sketch "Sketch3" profile of C1 L7 L8 L9 L10 L11 L12 C3 blind 5.5
extrude "Extrude22" cut sketch "Sketch3" + "Sketch1" profile of S1:C1 S1:L7 S1:L8 S1:L9 S1:L10 S1:L11 S1:L12 S1:C2 blind -7
chamfer "Chamfer11" distance 0.8
chamfer "Chamfer13" sketch "Sketch1" distance 2.5
fillet "Fillet10" radius 2
component_insert "Component Insert3"
joint "Assemble3" alignAngle 180 alignOffsetX 0 alignOffsetY 0 alignOffsetZ 0
component_insert "Component Insert1" sketch "Sketch1"
component_insert "Component Insert4" sketch "Sketch1"
joint "Assemble6" alignAngle -90 alignOffsetX 4.5 alignOffsetY 0 alignOffsetZ 0
component_insert "Component Insert5" sketch "Sketch1"
joint "Assemble7" alignAngle 0 alignOffsetX 0 alignOffsetY 0 alignOffsetZ 0
component_insert "Component Insert6" sketch "Sketch1"
joint "Assemble8" alignAngle 0 alignOffsetX 0 alignOffsetY 0 alignOffsetZ -0.2
sketch "Sketch4" plane through (0, 0, -21.4) normal (0, 0, -1) x axis (1, 0, 0)
  line L1 (-25.65, 0) -> (5.5, 0)
  line L2 (38.75, -33.4) -> (-41, -33.4)
  line L3 (17.15, -23.25) -> (17.15, -23.4)
  line L4 (5.5, -23.25) -> (17.15, -23.25)
  line L5 (5.5, 0) -> (5.5, -23.25)
  line L6 (-5.5, -10.5) -> (5.5, -10.5)
  line L7 (-5.5, 0) -> (-5.5, -10.5)
  line L8 (-25.65, -21.4) -> (-25.65, 0)
  line L9 (-41, -23.4) -> (-27.65, -23.4)
  line L10 (-41, -33.4) -> (-41, -23.4)
  line L11 (17.15, -23.4) -> (38.75, -23.4)
  line L12 (38.75, -23.4) -> (38.75, -33.4)
  circle C1 centre (0, -8.4) radius 2.625
  arc A1 centre (-27.65, -21.4) radius 2 clockwise from (-25.65, -21.4) to (-27.65, -23.4)
  point P9 (5.5, -10.5)
  point P11 (-5.5, 0)
  point P3 (5.5, 0)
  point P2 (0, -8.4)
  point P1 (0, 0)
  coincident L5 P9
  perpendicular L5 L6
  coincident L1 P11
  perpendicular L1 L7
  dimension "d198" distance P3 L6 = 10.5
  dimension "d199" distance P2 P9 = 5.5
  dimension "d200" distance P1 L7 = 5.5
extrude "Extrude25" add sketch "Sketch4" + "Sketch1" profile of S1:C1 S1:L1 S1:L5 S1:L6 S1:L7 blind 35
chamfer "Chamfer14" distance 0.8
fillet "Fillet12" radius 2
extrude "Extrude26" cut sketch "Sketch1" along a picked direction blind -1.25
joint "Assemble9" alignAngle 180 alignOffsetX 0 alignOffsetY 0 alignOffsetZ -19
component_insert "Component Insert7" sketch "Sketch1"
joint "Assemble10" alignAngle 180 alignOffsetX 0 alignOffsetY 0 alignOffsetZ 0
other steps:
joint_origin "JointOrigin3"
joint_origin "JointOrigin4"
joint_origin "JointOrigin6"
joint_origin "JointOrigin7"

design "Heater Module Circuit"
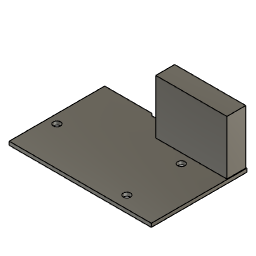
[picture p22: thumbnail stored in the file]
sketch "Sketch1" plane through (0, 0, 0) normal (0, 0, 1) x axis (1, 0, 0)
  line L1 (64, 0) -> (0, 0)
  line L2 (64, 43) -> (64, 0)
  line L3 (0, 0) -> (0, 43)
  line L4 (47.5, 5.5) -> (47.5, 30)
  line L5 (63.75, 42.75) -> (31.75, 42.75)
  line L6 (63.75, 34.25) -> (63.75, 42.75)
  line L7 (31.75, 34.25) -> (63.75, 34.25)
  line L8 (31.75, 42.75) -> (31.75, 34.25)
  line L9 (30.25, 42) -> (31.25, 43)
  line L10 (22.25, 42) -> (30.25, 42)
  line L11 (21.25, 43) -> (22.25, 42)
  line L12 (31.25, 43) -> (64, 43)
  line L13 (0, 43) -> (21.25, 43)
  line L14 (54.25, 41) -> (41.25, 41)
  line L15 (54.25, 36) -> (54.25, 41)
  line L16 (41.25, 36) -> (54.25, 36)
  line L17 (41.25, 41) -> (41.25, 36)
  line L18 (63.75, 42.75) -> (31.75, 34.25)
  line L19 (54.25, 36) -> (41.25, 41)
  circle C1 centre (4, 17.5) radius 1.625
  circle C2 centre (47.5, 30) radius 1.625
  circle C3 centre (47.5, 5.5) radius 1.625
  point P1 (0, 0)
  point P2 (0, 0)
  point P6 (47.5, 30)
  point P9 (47.5, 30)
  point P7 (47.5, 5.5)
  point P10 (47.5, 5.5)
  point P18 (21.25, 43)
  point P4 (64, 43)
  point P5 (0, 43)
  point P8 (4, 17.5)
  point P13 (63.75, 34.25)
  point P14 (31.75, 34.25)
  point P11 (31.75, 42.75)
  point P15 (31.25, 43)
  point P19 (41.25, 41)
  point P22 (41.25, 36)
  point P20 (54.25, 41)
  horizontal L1
  vertical L2
  horizontal L12
  vertical L3
  coincident P1 P2
  vertical L4
  coincident P6 P9
  coincident P7 P10
  equal C2 C3
  equal C1 C3
  horizontal L5
  vertical L6
  horizontal L7
  vertical L8
  parallel L10 L12
  coincident P18 L12
  perpendicular L9 L11
  collinear L12 L13
  horizontal L14
  vertical L15
  horizontal L16
  vertical L17
  midpoint L18 L19
  dimension "d1" distance P4 P5 = 64
  dimension "d2" distance P2 P5 = 43
  dimension "d3" distance P8 L12 = 25.5
  dimension "d4" distance P10 L12 = 37.5
  dimension "d5" distance P9 L12 = 13
  dimension "d6" diameter C1 = 3.25
  dimension "d7" distance L3 P8 = 4
  dimension "d8" distance L3 L4 = 47.5
  dimension "d9" distance P4 L6 = 0.25
  dimension "d10" distance L5 L12 = 0.25
  dimension "d11" distance P13 P14 = 32
  dimension "d12" distance P11 P14 = 8.5
  dimension "d13" angle L11 L12 = 45
  dimension "d14" distance L10 L12 = 1
  dimension "d15" distance P11 P15 = 0.5
  dimension "d16" distance P15 P18 = 10
  dimension "d21" distance P19 P22 = 5
  dimension "d22" distance P19 P20 = 13
extrude "Extrude1" new body sketch "Sketch1" profile of L1 L2 L13 L3 C1 C2 C3 L5 L6 L7 L8 L9 L10 L11 along normal blind 1.6
extrude "Extrude2" add sketch "Sketch1" profile of L5 L6 L7 L8 along normal blind 26
extrude "Extrude3" add sketch "Sketch1" profile of L14 L15 L16 L17 against normal blind 2

design "AS_Hotend-Circuits" references "Heater Module Circuit", "Loadcell Amp Circuit"
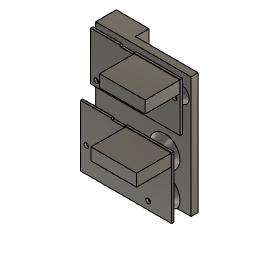
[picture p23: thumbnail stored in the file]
sketch "Sketch1" plane through (0, 0, 0) normal (1, 0, 0) x axis (0, 1, 0)
  line L1 (0, 50) -> (0, 0)
  line L2 (-11, 55) -> (-11, -5)
  line L3 (3.5, -5) -> (-11, -5)
  line L4 (3.5, 55) -> (3.5, -5)
  line L5 (-11, 55) -> (3.5, 55)
  line L6 (-6, 55) -> (-6, -5)
  line L7 (3.5, 80) -> (3.5, 55)
  line L8 (-11, 80) -> (3.5, 80)
  line L9 (-11, 55) -> (-11, 80)
  line L10 (-6, 80) -> (-6, 55)
  circle C1 centre (0, 0) radius 2.75
  circle C2 centre (0, 50) radius 2.75
  circle C3 centre (0, 50) radius 5
  circle C4 centre (0, 0) radius 5
  point P1 (0, 0)
  point P2 (0, 0)
  point P4 (0, 0)
  point P3 (0, 50)
  point P5 (0, 50)
  point P7 (-11, 55)
  point P10 (-11, 55)
  point P13 (-6, -5)
  point P14 (-6, 55)
  point P17 (-11, 55)
  point P18 (-6, 80)
  point P11 (0, 50)
  point P8 (3.5, -5)
  point P15 (3.5, 80)
  coincident P1 P2
  vertical L1
  coincident P1 P4
  coincident P3 P5
  equal C1 C2
  vertical L2
  perpendicular L2 L3
  perpendicular L3 L4
  perpendicular L4 L5
  coincident P7 P10
  concentric C2 C3
  concentric C1 C4
  equal C3 C4
  tangent L5 C3
  tangent L3 C4
  coincident L3 P13
  coincident L5 P14
  perpendicular L5 L6
  perpendicular L5 L7
  perpendicular L4 L8
  perpendicular L8 L9
  coincident P10 P17
  coincident L8 P18
  perpendicular L8 L10
  dimension "d1" distance P2 P3 = 50
  dimension "d2" diameter C2 = 5.5
  dimension "d3" diameter C3 = 10
  dimension "d4" distance P7 L6 = 5
  dimension "d5" distance P11 L6 = 6
  dimension "d10" distance P8 P15 = 85
  dimension "d40" distance L4 P11 = 3.5
extrude "Extrude1" new body sketch "Sketch1" profile of C1 C2 L3 L4 L5 L6 L7 L8 L10 along normal blind 11
extrude "Extrude2" add sketch "Sketch1" profile of L2 L3 L5 L6 L8 L9 L10 along normal blind 67
component_insert "Component Insert1"
component_insert "Component Insert2"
